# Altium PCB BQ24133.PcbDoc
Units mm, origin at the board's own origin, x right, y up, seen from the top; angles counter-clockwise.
Board outline 30 x 50.01 mm, 2 copper layers (Top Layer, Bottom Layer); 56 components, 30 nets, 146 pads, 36 vias.
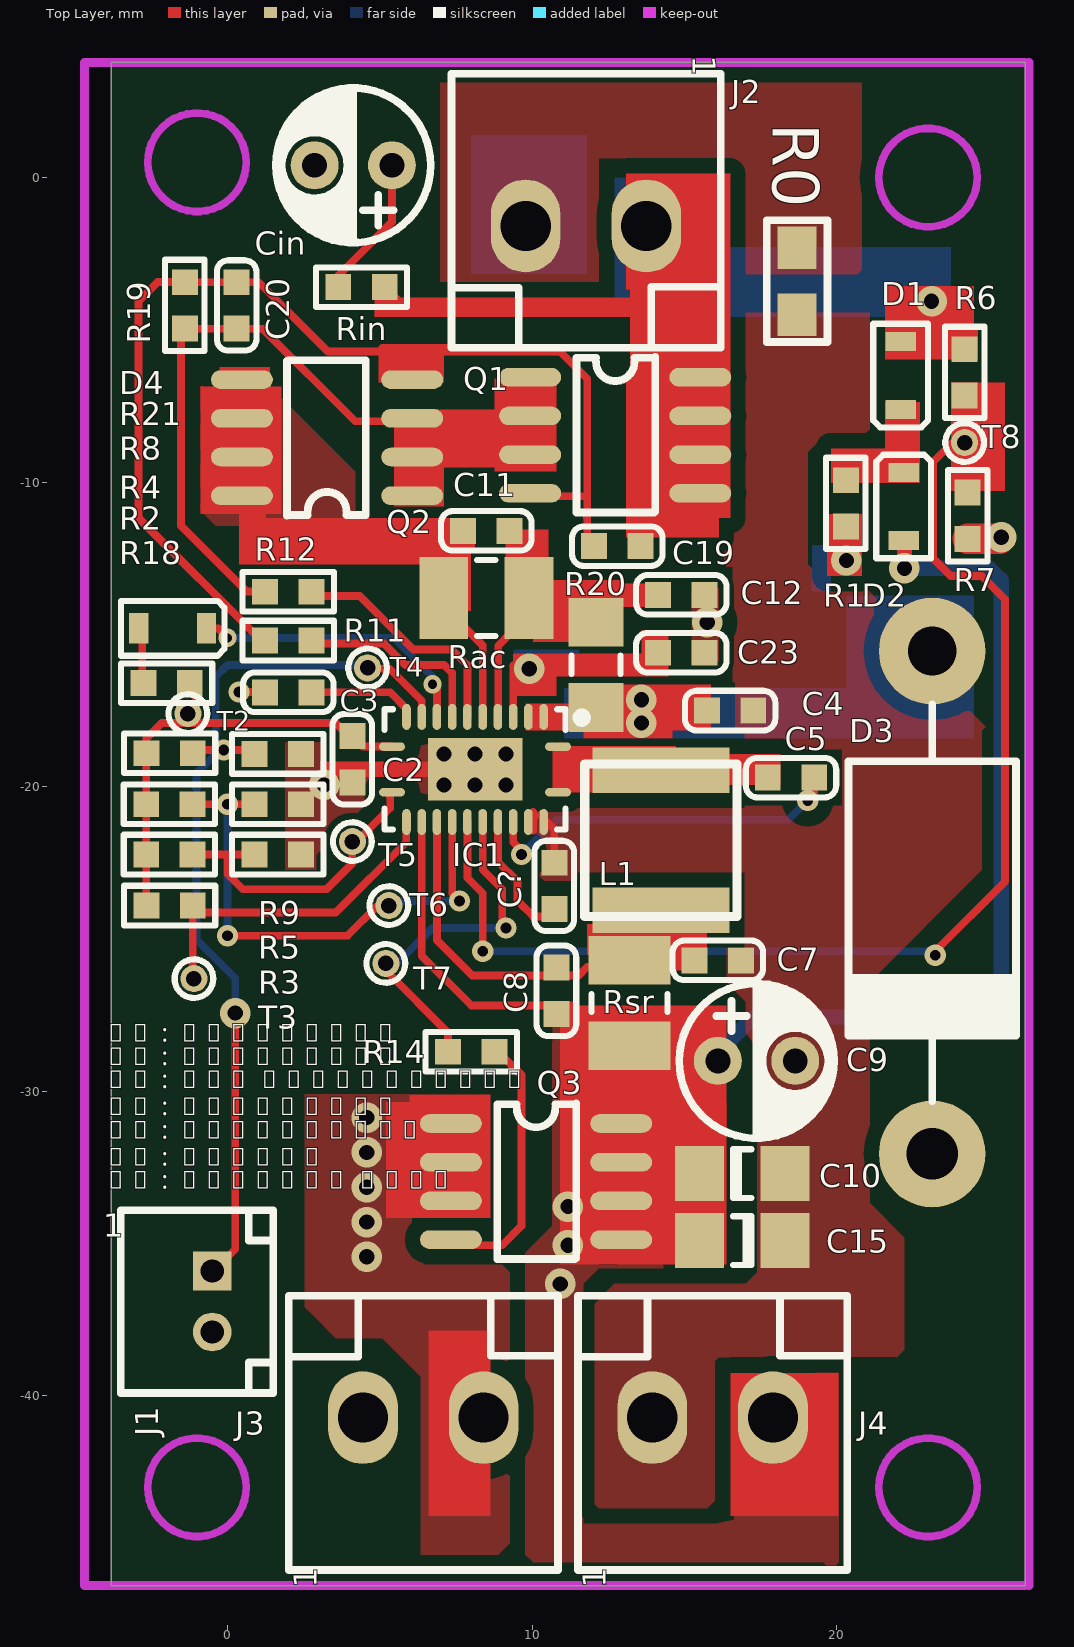
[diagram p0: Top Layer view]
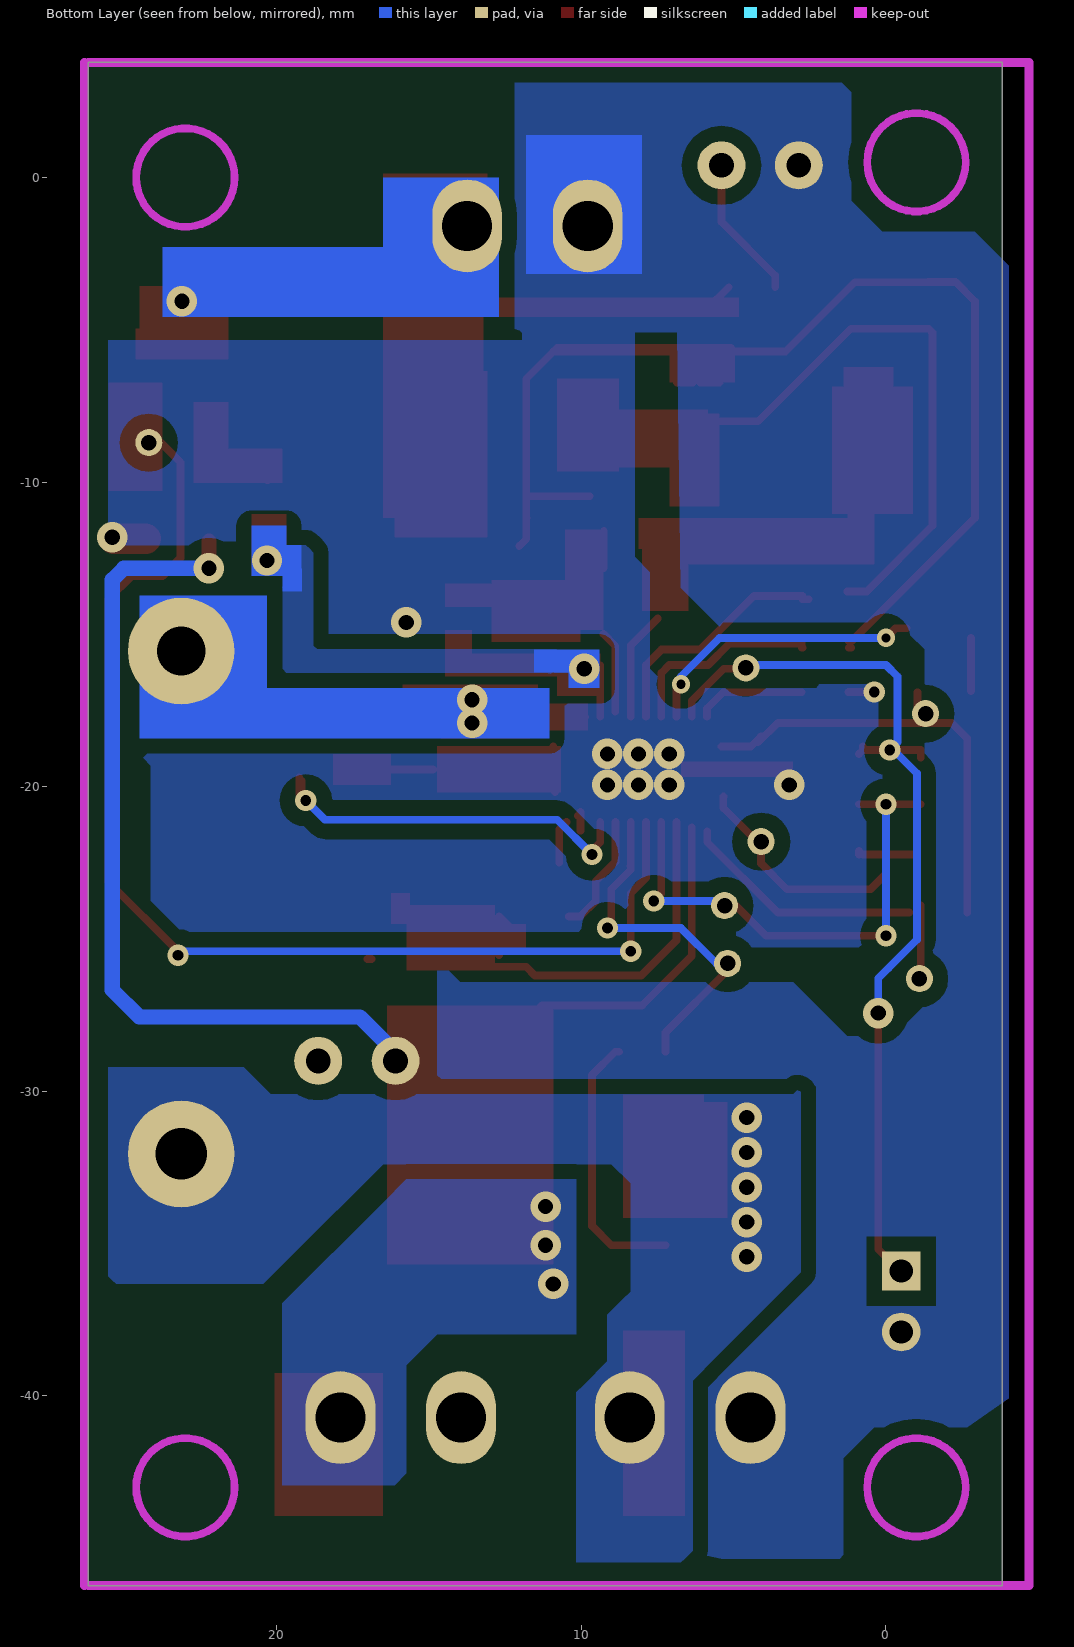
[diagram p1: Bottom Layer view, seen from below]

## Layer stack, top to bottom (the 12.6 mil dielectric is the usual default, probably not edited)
Top Layer: signal copper 0.0356
Dielectric: dielectric 0.32, FR-4, Dk 4.8
Bottom Layer: signal copper 0.0356

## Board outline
-3.81,3.772 -3.8,3.782 26.19,3.782 26.19,-46.228 -3.81,-46.228

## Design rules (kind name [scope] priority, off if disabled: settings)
Clearance [All] p1: gap=0.2
ComponentClearance [All] p1: gap=0.254 collisioncheckmode=3 verticalgap=0.254
PolygonConnect [All] p1: connectstyle=Direct reliefconductorwidth=0.254 reliefentries=4 polygonreliefangle="90 Angle"
RoutingVias [All] p1: holewidth=0.711 width=1.27 viastyle="Through Hole" minholewidth=0.711 minwidth=1.27 maxholewidth=0.711 maxwidth=1.27
SolderMaskExpansion [All] p1: expansion=0.102
TestPointUsage [All] p1: valid=0 allowmultiple=FALSE
Testpoint [All] p1: side=15 testpointundercomponent=TRUE minsize=1.016 maxsize=2.54 preferedsize=1.524 minholesize=0 maxholesize=1.016 preferedholesize=0.813 testpointgrid=0.025 style=1023 order=0-112345678
Width [All] p1: maxlimit=1.2 minlimit=0.254 preferedwidth=1
18 further rules are at their usual default settings.

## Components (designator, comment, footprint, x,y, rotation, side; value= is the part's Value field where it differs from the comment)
C2 "106" C0603 4.1,-19.1 r270 top
C3 "106" C0603 2,-16.9 r0 top
C4 "106" C0603 16.5,-17.5 r180 top
C5 "0.047uf" C0603 18.5,-19.7 r0 top
C7 "104" C0603 16.1,-25.7 r0 top
C8 "105" C0603 10.8,-26.7 r270 top
C9 "10uF/15V" RB.10#1 16.1,-29 r0 top
C10 "106" C1206 16.9,-32.7 r0 top
C11 "104" C0603 8.5,-11.6 r0 top
C12 "104" C0603 14.9,-13.7 r0 top
C15 "106" C1206 16.9,-34.9 r180 top
C19 "472" C0603 12.8,-12.1 r180 top
C20 "473" C0603 0.3,-4.2 r270 top
C23 "106" C0603 14.9,-15.6 r0 top
C? "104" C0603 10.73,-23.257 r270 top
Cin "2.2uF/25V" RB.10#2 5.4,0.4 r180 top
D1 "1N5819" SOD-323 22.1,-6.5 r270 top
D2 "1N5819" SOD-323 22.2,-10.8 r90 top
D3 "6A10" 6A10 16.1,-31 r0 top
D4 "1N5819" SOD-323 -1.8,-14.8 r0 top
IC1 "BQ24133" LC-VQFN-24_3.5x5.5x05P 8.128,-19.431 r180 top (schematic designator *)
J1 "NTC" PH2 -0.5,-36.9 r270 top
J2 "Vin" VH3.96-2A 11,-2.3 r270 top
J3 "Vsys" VH3.96-2A 7.2,-40 r90 top
J4 "VBAT" VH3.96-2A 16.7,-40 r90 top
L1 "6.8uh" SWPA5040S6R8 16.73,-24.257 r180 top
Q1 "N-MOSFET" SOIC-8 14,-11 r0 top
Q2 "N-MOSFET" SOIC-8 2,-6 r180 top
Q3 "P-MOSFET" SOIC-8 11.4,-35.5 r0 top
R0 "0" 0805 18.7,-3.4 r90 top
R1 "10" 0603 20.3,-10.7 r270 top
R2 "232K" 0603 -1.905,-22.225 r180 top
R3 "32.4K" 0603 1.651,-22.225 r180 top
R4 "100K" 0603 -1.905,-20.574 r0 top
R5 "57.14K" 0603 1.651,-20.574 r0 top
R6 "1000K" 0603 24.2,-6.4 r270 top
R7 "110K" 0603 24.3,-11.1 r270 top
R8 "5.23K" 0603 -1.9,-18.9 r0 top
R9 "30.1K" 0603 1.651,-18.923 r0 top
R11 "4.02K" 0603 2,-15.2 r0 top
R12 "4.02K" 0603 2,-13.6 r180 top
R14 "1K" 0603 8,-28.7 r180 top
R18 "0" 0603 -1.9,-23.9 r0 top
R19 "499K" 0603 -1.4,-4.2 r270 top
R20 "0" 3216[1206] 12.1,-16 r90 top
R21 "5.1K" 0603 -2,-16.6 r180 top
Rac "20m" 3225[1210] 8.5,-13.8 r180 top
Rin "2" 0603 4.4,-3.6 r180 top
Rsr "20m" 3225[1210] 13.2,-27.1 r90 top
T2 "TEST" SIP-1 -1.3,-17.6 r90 top
T3 "TEST" SIP-1 -1.1,-26.3 r90 top
T4 "TEST" SIP-1 4.6,-16.1 r90 top
T5 "TEST" SIP-1 4.1,-21.8 r90 top
T6 "TEST" SIP-1 5.3,-23.9 r90 top
T7 "TEST" SIP-1 5.2,-25.8 r90 top
T8 "TEST" SIP-1 24.2,-8.7 r90 top

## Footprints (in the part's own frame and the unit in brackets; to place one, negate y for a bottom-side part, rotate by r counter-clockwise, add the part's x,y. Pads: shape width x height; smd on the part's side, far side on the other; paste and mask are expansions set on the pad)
6A10 [mm]
  round 3.5 hole 1.6: 1(7.036,15.454)
  round 3.5 hole 1.69: 2(7.036,-1.056)
  silkscreen extent 4.29,0.68 9.79,13.7
0603 [mm]
  rect 0.85x0.85 smd: 1(-0.762,0) 2(0.762,0)
  silkscreen extent -1.5,-0.65 1.5,0.65
0805 [mm]
  rect 1.4x1.27 smd: 1(-1.1,0) 2(1.1,0)
  silkscreen extent -2,-1 2,1
3216[1206] [mm]
  rect 1.6x1.8 smd: 1(-1.4,0) 2(1.4,0)
  silkscreen extent -0.3,-0.8 0.3,0.8
3225[1210] [mm] "Chip Resistor; Body 3.2 x 2.5 mm (LxW typ)"
  rect 1.6x2.7 smd: 1(-1.4,0) 2(1.4,0)
  silkscreen extent -0.3,-1.25 0.3,1.25
C0603 [mm]
  rect 0.85x0.85 smd: 1(-0.762,0) 2(0.762,0)
  silkscreen extent -1.49,-0.65 1.49,0.65
C1206 [mm]
  rect 1.6x1.8 smd: 1(-1.4,0) 2(1.4,0)
  silkscreen extent -0.3,-0.8 0.3,0.8
LC-VQFN-24_3.5x5.5x05P [mm]
  oval 0.85x0.28 smd paste-0.025 mask+0.051: 1(-2.725,-0.75) 12(2.725,-0.75) 13(2.725,0.75) 24(-2.725,0.75)
  oval 0.28x0.85 smd paste-0.025 mask+0.051: 2(-2.25,-1.725) 3(-1.75,-1.725) 4(-1.25,-1.725) 5(-0.75,-1.725) 6(-0.25,-1.725) 7(0.25,-1.725) 8(0.75,-1.725) 9(1.25,-1.725) 10(1.75,-1.725) 11(2.25,-1.725) 14(2.25,1.725) 15(1.75,1.725) 16(1.25,1.725) 17(0.75,1.725) 18(0.25,1.725) 19(-0.25,1.725) 20(-0.75,1.725) 21(-1.25,1.725) 22(-1.75,1.725) 23(-2.25,1.725)
  rect 3.1x2.05 smd paste-1.025 mask+0.051: GND(0,0)
  silkscreen extent -3.65,-1.97 2.98,1.97
PH2 [mm]
  rect 1.27x1.27 hole 0.762: 1(-1,0)
  round 1.27 hole 0.762: 2(1,0)
  silkscreen extent -3,-3 3,2
RB.10#1 [mil]
  round 62 hole 32: 1(0,0) 2(100,0)
  silkscreen extent -50,-100 150,100
RB.10#2 [mil]
  round 62 hole 32: 1(0,0)
  round 62.01 hole 32.01: 2(100,0)
  silkscreen extent -50,-100 150,100
SIP-1 [mil]
  round 35 hole 20: 1(0,0)
  silkscreen extent -25,-25 25,25
SOD-323 [mm]
  rect 0.63x1 smd: 1(-1.115,0) 2(1.115,0)
  silkscreen extent -1.7,-0.9 1.7,0.9
SOIC-8 [mil]
  oval 80x24.02 smd: 1(-160,175) 8(60,175)
  oval 80x24 smd: 2(-160,125) 3(-160,75) 4(-160,25) 5(60,25) 6(60,75) 7(60,125)
  silkscreen extent -100,0 2,201
SWPA5040S6R8 [mm]
  rect 4.5x1.5 smd: 1(2.5,-4.8) 2(2.5,-0.2)
  silkscreen extent 0,-5 5,0
VH3.96-2A [mil]
  oval 120x90 hole 65: 1(-27.95,108.31) 2(-27.95,-47.6)
  silkscreen extent -225,-144 130,204

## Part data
C2 C3 C5 C7 C8 C11 C12 C19 C20 C?: library part CAP, "Capacitor"
C9 Cin: library part ELECTRO1, "Electrolytic Capacitor"
D1 D2 D3: library part DIODE
J1 J2 J3 J4: library part "Header 2", "Header, 2-Pin"
L1: library part Inductor, "Inductor"
Q3: library part N-MOSFET
R1 R2 R3 R4 R5 R6 R7 R8 R9 R11 R12 R14 R18 R19 Rac Rin Rsr: library part RES2

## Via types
v1: diameter 1, hole 0.5, Top Layer to Bottom Layer, 24 vias
v2: diameter 0.7, hole 0.35, Top Layer to Bottom Layer, 10 vias
v3: diameter 0.6, hole 0.3, Top Layer to Bottom Layer, 2 vias

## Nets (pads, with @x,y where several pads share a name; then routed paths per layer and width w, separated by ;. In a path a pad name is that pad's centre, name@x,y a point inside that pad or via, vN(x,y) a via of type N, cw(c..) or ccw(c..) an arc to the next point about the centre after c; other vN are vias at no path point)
13.5V: C19.1 D1.1 J2.1 Q1.5 Q1.6 Q1.7 Q1.8 R6.1 Rin.1 | length 11.4
  Top Layer w0.254: Rin.1 5.88,-4.318 13.97,-4.318 ; D1.1@22.098,-5.207 22.225,-5.207 22.352,-5.334 R6.1@24.003,-5.334 ; R6.1@23.947,-5.385 R6.1
  other v1: 23.114,-4.064
ACDRV: IC1.8 R11.2 | length 6.5
  Top Layer w0.254: R11.2@2.741,-15.439 R11.2@2.762,-15.439 ; R11.2@2.762,-15.3 5.14,-15.3 5.842,-16.002 7.112,-16.002 7.378,-16.268 IC1.8
ACN: C11.2 C12.1 IC1.5 R20.2 Rac.1 | length 5.1
  Top Layer w0.254: IC1.5@8.89,-17.526 8.89,-15.367 Rac.1@9.271,-14.986 ; Rac.1@9.262,-12.818 C11.2 ; Rac.1@9.462,-13.653 Rac.1@9.462,-12.5
ACP: C11.1 IC1.6 Q2.5 Q2.6 Q2.7 Q2.8 Rac.2 | length 3.6
  Top Layer w0.254: Rac.2@7.493,-14.478 8.378,-15.363 IC1.6
ACSET: IC1.17 R4.2 R5.1 T6.1 | length 17.3
  Top Layer w0.254: R4.2 R5.1 ; v2(0,-24.892) 3.937,-24.892 4.924,-23.905 5.305,-23.905 T6.1@5.461,-23.749 ; IC1.17 7.378,-23.507 v2(7.62,-23.749)
  Bottom Layer w0.254: v2(0,-24.892) v2(0,-20.574) ; T6.1@5.461,-23.749 v2(7.62,-23.749) v2@7.747,-23.876
AVCC: C23.1 IC1.4 R1.2 | length 2
  Top Layer w0.254: IC1.4 9.378,-16.022 ; 13.716,-15.113 13.727,-15.113 ; 14.038,-15.172 14.224,-14.986
  other v1: 9.906,-16.129 20.32,-12.573
B\A\T\D\R\V\: IC1.19 R14.2 T7.1 | length 12.1
  Top Layer w0.254: T7.1@5.207,-25.654 5.207,-26.035 7.238,-28.066 R14.2 ; 8.378,-22.602 8.386,-22.61 ; IC1.19 8.378,-22.729 9.017,-23.368 9.017,-24.511 v2(9.144,-24.638)
  Bottom Layer w0.254: T7.1 5.569,-25.8 6.731,-24.638 v2(9.144,-24.638)
BTST: C5.2 IC1.21 | length 12.5
  Top Layer w0.254: IC1.21 9.378,-21.824 9.652,-22.098 v2(9.652,-22.225) ; v2(19.047,-20.45) 19.177,-20.32 C5.2@19.177,-19.812 ; v2@19.262,-20.235 C5.2
  Bottom Layer w0.254: v2(9.652,-22.225) 10.795,-21.082 18.415,-21.082 v2(19.047,-20.45)
CELL: IC1.14 R18.2 T3.1 | length 10.4
  Top Layer w0.254: R18.2 -1.138,-26.262 T3.1 ; R18.2@-0.762,-24.13 3.556,-24.13 5.87,-21.816 IC1.14@5.87,-21.463
CMSRC: IC1.7 R12.1 | length 8
  Top Layer w0.254: R12.1@2.54,-13.843 R12.1@2.741,-13.843 ; R12.1@2.741,-13.739 4.341,-13.739 6.096,-15.494 7.366,-15.494 7.878,-16.006 7.878,-17.275 IC1.7
GATE: C19.2 C20.1 Q1.4 Q2.4 R11.1 R19.1 | length 43.2
  Top Layer w0.254: R19.1 1.025,-3.438 3.302,-5.715 5.588,-5.715 ; R19.1@-1.4,-3.429 -2.286,-3.429 -2.921,-4.064 -2.921,-11.176 1.103,-15.2 R11.1 ; R11.1@1.143,-15.439 R11.1@1.217,-15.439 ; 5.08,-5.588 10.795,-5.588 11.811,-6.604 11.811,-11.873 C19.2 ; Q2.4@5.461,-6.731 Q2.4@6.096,-6.731 ; Q2.4@6.343,-6.739 Q2.4@6.723,-6.739 ; 6.477,-5.842 6.604,-5.715 10.922,-5.715 ; Q2.4@6.858,-6.731 Q2.4@6.858,-6.604 ; Q1.4@9.736,-10.465 11.735,-10.465 11.811,-10.541 ; 11.8,-11.165 11.811,-11.176
GND: C2.2 C3.1 C12.2 C23.2 Cin.2 IC1.GND J1.2 J2.2 J3.1 R0.2 R3.1 R5.2 R7.2 R9.2 | length 2
  Top Layer w0.254: v2(0.381,-16.891) 1.229,-16.891 C3.1 ; v1@25.349,-11.862 v1(25.4,-11.811)
  Top Layer w1: R7.2 v1@25.349,-11.862
  other v1: 3.175,-19.939 7.112,-19.939 8.128,-19.939 9.144,-19.939 7.112,-18.923 8.128,-18.923 9.144,-18.923 15.748,-14.605
ISET: IC1.13 R2.1 R3.2 T5.1 | length 10.1
  Top Layer w0.254: R2.1@-1.016,-22.225 R3.2@0.762,-22.225 ; 0,-22.225 0,-22.86 0.508,-23.368 3.252,-23.368 4.1,-22.52 4.1,-21.935 5.34,-20.695 ; R3.2 R3.2@0.889,-22.098 ; T5.1 T5.1@4.235,-21.8 ; IC1.13@5.334,-20.32 5.346,-20.332 5.346,-20.695
NetC3_2: C3.2 IC1.11 | length 3.6
  Top Layer w0.254: C3.2 5.343,-16.9 5.878,-17.435 IC1.11
NetC5_1: C5.1 IC1.1 IC1.24 L1.1 | length 4.3
  Top Layer w0.254: IC1.24 IC1.24@10.922,-20.112 ; IC1.24@10.922,-20.066 IC1.1@10.922,-18.669 ; L1.1@14.859,-19.431 C5.1@17.653,-19.431
NetC20_2: C20.2 Q1.1 Q1.2 Q1.3 Q2.1 Q2.2 Q2.3 R12.2 R19.2 | length 18.8
  Top Layer w0.254: R12.2@1.27,-13.589 0.635,-13.589 -1.524,-11.43 -1.524,-5.086 R19.2 1.152,-4.962 4.191,-8.001 Q2.3@5.969,-8.001
NetC?_2: C?.2 IC1.20 | length 4
  Top Layer w0.254: IC1.20 8.878,-22.46 9.525,-23.107 9.525,-23.749 10.033,-24.257 C?.2@10.414,-24.257
NetCin_1: Cin.1 Rin.2 | length 4.7
  Top Layer w0.254: Rin.2 3.638,-3.22 5.4,-1.458 Cin.1
NetD1_2: D1.2 D2.2 R1.1 | length 4.1
  Top Layer w0.254: R1.1 20.459,-9.779 22.098,-9.779 22.225,-9.652 D1.2@22.225,-7.62
NetD4_1: D4.1 R21.2 | length 1.7
  Top Layer w0.254: R21.2@-2.794,-16.856 D4.1@-2.794,-15.113
NetQ3_4: Q3.4 R14.1 | length 8.8
  Top Layer w0.254: Q3.4@7.239,-35.052 9.017,-35.052 9.652,-34.417 9.652,-29.464 8.888,-28.7 R14.1
OVPSET: IC1.18 R6.2 R7.1 T8.1 | length 39.6
  Top Layer w0.254: IC1.18 7.878,-22.991 8.382,-23.495 v2(8.382,-25.4) ; v2(23.241,-25.527) 23.241,-25.4 25.527,-23.114 25.527,-13.843 24.765,-13.081 23.749,-13.081 23.16,-12.492 23.16,-9.352 23.812,-8.7 T8.1 T8.1@24.2,-8.947
  Bottom Layer w0.254: v2(8.382,-25.4) 23.114,-25.4 v2(23.241,-25.527)
PGND: C4.1 C7.2 C9.2 C10.2 C15.1 C?.1 IC1.22 IC1.23 J4.1 R0.1 | length 2.3
  Top Layer w0.254: 10.031,-21.441 10.031,-20.828 ; 10.031,-20.956 10.105,-20.956 10.113,-20.948 ; IC1.23@10.488,-21.156 10.73,-21.398 C?.1 ; C7.2@16.891,-25.654 C7.2@17.018,-25.654
PVCC: C4.2 D3.1 IC1.2 IC1.3 R20.1 | length 0.5
  Top Layer w0.254: IC1.3 IC1.2
  other v1: 13.589,-17.907 13.589,-17.145
SRN: C8.2 C9.1 C10.1 C15.2 D2.1 IC1.15 J4.2 Q3.5 Q3.6 Q3.7 Q3.8 Rsr.1 | length 39.4
  Top Layer w0.254: IC1.15@6.378,-21.336 6.378,-25.555 8.001,-27.178 11.303,-27.178 Rsr.1@12.065,-27.94 ; Q3.5@12.787,-34.965 Q3.5@13.024,-34.965
  Top Layer w0.5: v1(22.225,-12.827) D2.1@22.225,-11.94
  Bottom Layer w0.254: C9.1@16.129,-29.083 C9.1@16.129,-29
  Bottom Layer w0.5: C9.1 16.1,-28.731 17.272,-27.559 24.511,-27.559 25.4,-26.67 25.4,-13.208 25.019,-12.827 v1@22.098,-12.827
  other v1: 10.922,-36.322 11.176,-35.052 11.176,-33.782
SRP: C7.1 C8.1 IC1.16 L1.2 Rsr.2 | length 13.8
  Top Layer w0.254: IC1.16 6.878,-25.039 8.034,-26.195 11.524,-26.195 11.811,-25.908 Rsr.2@12.827,-25.908 ; L1.2@12.319,-24.638 12.7,-24.257 Rsr.2@12.7,-25.527 ; L1.2@13.335,-24.003 L1.2@14.351,-24.003 ; L1.2@13.589,-24.257 L1.2@13.716,-24.13 ; L1.2@13.716,-24.257 L1.2@13.97,-24.003
START: D4.2 IC1.9 | length 9.2
  Top Layer w0.254: D4.2 -0.313,-14.8 v3(0,-15.113) ; v3(6.731,-16.637) 6.878,-16.784 6.878,-17.213 IC1.9
  Bottom Layer w0.254: v3(0,-15.113) 5.461,-15.113 v3@6.731,-16.383
SYSTEM: D3.2 J3.2 Q3.1 Q3.2 Q3.3
  other v1: 4.572,-35.433 4.572,-34.29 4.572,-33.147 4.572,-32.004 4.572,-30.861
TS: IC1.10 J1.1 R8.2 R9.1 T4.1 | length 31.8
  Top Layer w0.254: R8.2@-1.143,-19.05 R8.2@-1.143,-18.796 ; R8.2@-1.138,-18.796 R9.1@0.762,-18.796 ; J1.1 -0.467,-35.9 0.254,-35.179 v1(0.254,-27.432) ; R9.1@0.762,-18.669 R9.1@0.762,-18.796 ; R9.1 R9.1@0.762,-18.796 ; T4.1@4.699,-16.129 5.327,-16.129 6.378,-17.18 IC1.10
  Bottom Layer w0.254: J1.1 J1.1@-0.127,-35.527 ; -0.127,-25.908 -1.016,-25.019 -1.016,-19.558 -0.254,-18.796 v2(-0.127,-18.796) -0.381,-18.542 -0.381,-16.383 0,-16.002 4.318,-16.002 4.416,-16.1 T4.1 ; -0.088,-25.947 0.254,-26.289 v1@0.254,-27.559
VREF: C2.1 IC1.12 R2.2 R4.1 R8.1 R18.1 R21.1 T2.1 | length 15.5
  Top Layer w0.254: R18.1@-2.667,-24.13 -2.667,-18.415 -2.159,-17.907 3.556,-17.907 C2.1@4.191,-18.542 ; T2.1@-1.038,-17.885 R21.1@-1.038,-16.9 ; C2.1 4.443,-18.681 IC1.12

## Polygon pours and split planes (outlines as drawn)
GND on Top Layer (solid): 12.065,-3.683 11.938,-3.81 6.985,-3.81 6.985,3.175 20.828,3.175 20.828,-3.048 20.701,-3.175 17.018,-3.175 16.891,-3.048 16.637,-2.794 16.637,0.635 12.192,0.635 12.192,-3.556
ACP on Top Layer "Top Layer-ACP" (solid, pour order 1000): 1.143,-6.604 4.191,-9.652 4.191,-11.303 4.064,-11.43 -0.381,-11.43 -0.508,-11.303 -0.889,-10.922 -0.889,-6.604
SRN on Top Layer "Top Layer-SRN" (solid, pour order 1001): 20.066,-45.466 19.812,-45.72 19.558,-45.466 10.033,-45.466 9.779,-45.212 9.779,-35.306 10.668,-34.417 10.668,-27.559 11.049,-27.178 15.367,-27.178 16.637,-28.448 16.383,-28.702 16.383,-35.687 16.256,-35.814 12.192,-35.814 11.684,-36.322 11.684,-44.196 16.002,-44.196 16.637,-44.069 16.637,-39.37 16.764,-39.243 20.066,-39.243
SYSTEM on Top Layer "Top Layer-SYSTEM" (solid, pour order 1002): 5.969,-30.099 6.096,-30.226 9.144,-30.226 9.144,-34.036 9.017,-34.163 6.223,-34.163 6.223,-35.433 6.477,-35.687 9.017,-35.687 9.271,-35.941 9.525,-36.195 9.525,-44.577 8.89,-45.212 6.35,-45.212 6.35,-39.37 5.461,-38.481 5.08,-38.1 3.556,-38.1 2.794,-37.338 2.54,-37.084 2.54,-30.099
PGND on Top Layer "Top Layer-PGND" (solid, pour order 1003): 16.002,-43.434 15.748,-43.688 12.192,-43.688 11.938,-43.434 11.938,-37.084 12.7,-36.322 17.018,-36.322 17.399,-35.941 17.399,-28.956 17.018,-28.575 17.018,-27.051 16.383,-26.416 16.383,-25.146 16.891,-24.638 16.891,-23.368 16.637,-23.114 10.414,-23.114 9.652,-22.352 9.652,-20.574 9.906,-20.32 19.685,-20.32 20.066,-19.939 19.939,-19.812 19.939,-18.923 18.034,-18.923 17.78,-18.669 16.764,-18.669 16.256,-18.161 16.383,-4.445 21.082,-4.445 21.082,-8.255 20.828,-8.509 19.558,-8.509 19.05,-9.017 19.05,-12.7 19.812,-13.462 20.955,-13.462 21.336,-13.843 21.209,-13.97 21.209,-16.51 22.225,-17.526 24.384,-17.526 24.892,-18.034 24.765,-18.161 24.765,-22.733 21.082,-26.416 21.082,-33.655 22.225,-34.798 22.225,-38.481 21.971,-38.735 16.129,-38.735 16.002,-38.862
GND on Top Layer "Top Layer-GND" (solid, pour order 1004): 15.367,-13.462 16.129,-13.462 16.129,-15.875 16.002,-16.002 15.24,-16.002 15.24,-13.589
GND on Top Layer "Top Layer-GND 1" (solid, pour order 1005): 2.921,-22.733 1.905,-22.733 1.905,-18.415 3.048,-18.415 3.048,-18.542 3.429,-18.923 3.556,-19.05 5.842,-19.05 6.096,-18.796 6.477,-18.415 9.525,-18.415 9.652,-18.542 9.652,-20.447 6.35,-20.447 5.842,-19.939 5.207,-19.939 4.953,-20.193 2.921,-22.225
AVCC on Bottom Layer "Bottom Layer-AVCC" (solid, remove dead copper, pour order 1006): 10.541,-16.764 9.271,-16.764 9.271,-15.494 18.669,-15.494 18.796,-15.367 18.796,-12.319 18.923,-12.192 19.05,-12.065 20.828,-12.065 20.955,-12.192 21.082,-12.319 21.082,-12.7 20.828,-12.954 20.574,-13.208 20.193,-13.208 20.066,-13.335 19.939,-13.462 19.939,-16.002 19.685,-16.256 19.558,-16.383 11.049,-16.383 10.668,-16.764
GND on Bottom Layer "Bottom Layer-GND" (solid, pour order 1007): 0.889,-25.273 0.127,-24.511 0.127,-16.256 1.905,-16.256 2.286,-16.764 7.112,-16.764 7.747,-16.129 7.747,-12.954 8.255,-12.446 8.255,0.635 11.938,0.635 11.938,-5.334 26.035,-5.334 26.035,-12.319 23.622,-12.319 22.479,-11.938 18.542,-11.938 18.542,-15.367 18.415,-15.494 9.398,-15.494 9.017,-15.875 9.017,-17.018 10.668,-17.018 10.795,-17.145 10.795,-18.415 23.749,-18.415 24.384,-19.05 24.13,-19.304 24.13,-23.749 22.606,-25.273
SRN on Bottom Layer "Bottom Layer-SRN" (solid, pour order 1008): 10.16,-37.973 14.732,-37.973 15.113,-38.354 15.748,-38.989 15.748,-42.545 16.129,-42.926 19.812,-42.926 19.812,-36.957 16.51,-33.655 15.748,-32.893 10.16,-32.893
SYSTEM on Bottom Layer "Bottom Layer-SYSTEM" (solid, pour order 1009): 20.955,-29.337 21.082,-29.21 25.781,-29.21 25.908,-29.337 25.908,-35.687 25.4,-36.195 25.273,-36.322 20.447,-36.322 19.558,-35.433 16.51,-32.385 9.017,-32.385 8.382,-33.02 8.382,-36.576 8.636,-36.83 9.144,-37.338 9.144,-38.862 9.906,-39.624 10.16,-39.878 10.16,-45.466 6.731,-45.466 6.604,-45.339 6.35,-45.085 6.35,-39.497 5.588,-38.735 2.794,-35.941 2.794,-29.845 3.048,-30.099 20.193,-30.099
GND on Bottom Layer "Bottom Layer-GND 2" (solid, pour order 1011): 6.096,-45.339 6.096,-39.751 2.286,-35.941 2.286,-29.845 2.54,-29.591 14.605,-29.591 14.732,-29.464 14.732,-25.908 14.605,-25.781 13.97,-26.416 3.048,-26.416 1.27,-28.194 -0.254,-28.194 -1.27,-27.178 -1.27,-15.494 -0.381,-14.605 5.334,-14.605 5.461,-14.732 6.731,-13.462 6.858,-5.08 12.192,-5.08 12.192,3.302 1.651,3.302 1.143,2.794 1.143,-0.762 0.127,-1.778 -2.921,-1.778 -4.318,-3.175 -4.318,-39.878 -2.667,-41.021 0.381,-41.021 1.397,-42.037 1.397,-45.212 1.524,-45.339

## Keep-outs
Keep-Out Layer:
  circle w0.254: c-1,0.5 r1.616
  circle w0.254: c23,0 r1.616
  circle w0.254: c-1,-43 r1.616
  circle w0.254: c23,-43 r1.616
  lines w0.3: 24.511,3.772 26.18,3.772 26.19,3.782 ; 24.803,3.772 -4.699,3.772 -4.699,-46.228 26.19,-46.228 ; 26.317,-46.228 26.317,3.782

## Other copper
Top Layer:
  rectangle net GND: 3.048,-19.685 6.731,-19.177
  rectangle net 13.5V: 13.081,-3.683 16.51,0.127
  rectangle net AVCC: 13.589,-16.383 14.478,-14.859
  rectangle net AVCC: 9.378,-16.383 14.097,-15.621
  rectangle net AVCC: 9.378,-17.018 10.795,-15.748
  rectangle net NetC5_1: 16.256,-19.939 18.161,-18.923
  rectangle net NetC20_2: 5.842,-9.525 10.668,-7.62
  rectangle net ACP: 0.381,-12.7 7.938,-11.684
  rectangle net GATE: 4.953,-6.731 7.112,-5.715
  rectangle net ACP: 6.477,-14.224 8.001,-11.938
  rectangle net PVCC: 9.779,-18.161 12.7,-17.272
  rectangle net ACN: 9.271,-14.859 10.541,-11.557
  rectangle net NetC20_2: 8.763,-9.652 10.795,-6.604
  rectangle net NetC20_2: 5.461,-10.795 7.112,-7.747
  rectangle net NetC5_1: 10.668,-20.193 14.732,-18.669
  rectangle net 13.5V: 13.081,-11.811 16.129,-6.35
  rectangle net 13.5V: 13.208,-11.176 16.51,-3.429
  rectangle net ACP: 0.381,-11.811 1.27,-9.652
  rectangle net ACP: -0.254,-10.541 1.397,-6.223
  rectangle net 13.5V: 4.826,-4.572 13.97,-3.937
  rectangle net OVPSET: 23.749,-10.287 25.527,-6.731
  rectangle net 13.5V: 21.59,-5.969 24.638,-4.953
  rectangle net 13.5V: 21.59,-5.969 24.511,-3.556
  rectangle net SRN: 12.065,-35.306 16.383,-29.083
  rectangle net SRP: 11.811,-25.527 14.478,-24.511
  rectangle net SRP: 15.621,-24.511 16.256,-23.495
  rectangle net SRN: 16.51,-43.942 20.066,-39.243
  rectangle net SYSTEM: 5.969,-34.163 8.636,-30.099
  rectangle net SRN: 14.351,-29.464 15.875,-27.813
  rectangle net AVCC: 19.685,-13.081 20.828,-11.049
  rectangle net SRP: 12.827,-26.035 15.748,-23.876
  rectangle net NetD1_2: 21.59,-9.906 22.733,-7.366
  rectangle net NetD1_2: 19.812,-10.033 22.733,-8.89
  rectangle net PVCC: 11.43,-18.161 15.875,-16.637
  rectangle net PVCC: 11.684,-18.415 14.605,-16.764
  rectangle net ACP: 1.143,-12.192 8.128,-11.176
  rectangle net ACP: -0.889,-11.049 1.778,-6.86
  rectangle net SRN: 10.922,-35.687 16.383,-27.178
  rectangle net SYSTEM: 5.207,-34.163 7.366,-30.353
  rectangle net SYSTEM: 6.604,-43.942 8.636,-37.846
  rectangle net ACN: 10.033,-14.097 14.478,-13.335
  rectangle net ACN: 10.033,-15.24 12.954,-13.843
  rectangle net ACN: 10.541,-13.97 12.954,-13.208
Bottom Layer:
  rectangle net PVCC: 20.32,-18.415 24.511,-13.716
  rectangle net 13.5V: 13.081,-4.572 23.749,-2.286
  rectangle net 13.5V: 12.7,-4.572 16.51,0
  rectangle net AVCC: 9.398,-16.256 11.557,-15.494
  rectangle net AVCC: 9.398,-16.764 10.414,-15.875
  rectangle net AVCC: 19.192,-13.081 20.828,-12.065
  rectangle net AVCC: 19.177,-13.589 19.812,-12.827
  rectangle net AVCC: 19.685,-13.081 20.828,-11.43
  rectangle net GND: 8.001,-3.175 11.811,1.397
  rectangle net PVCC: 11.049,-18.415 24.384,-16.764

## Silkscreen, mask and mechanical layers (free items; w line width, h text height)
Top Overlay:
  text "T2：Vref=3.3v" at -4.064,-28.575 h1
  text "T3：CELL=3.3V" at -4.064,-29.337 h1
  text "T4：NTC =2.43-1.48V" at -4.064,-30.099 h1
  text "T5：ISET=0.4V" at -4.064,-30.988 h1
  text "T6：ACSET=1.2V" at -4.064,-31.75 h1
  text "T7：BATDRV" at -4.064,-32.639 h1
  text "T8：OVPSET= 0.5V" at -4.064,-33.401 h1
